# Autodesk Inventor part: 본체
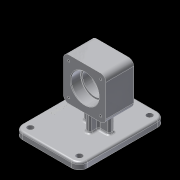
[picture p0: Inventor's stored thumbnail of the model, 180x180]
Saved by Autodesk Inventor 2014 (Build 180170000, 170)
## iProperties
Created: 2020-11
Part Number: 본체
Material: 알루미늄 6061
Document SubType Name: Modeling
Designer: kh
Density: 2.71 g/cm^3
Appearance: 알루미늄 - 평지
Mass: 685.745 g
Surface Area: 542.794 cm^2
Volume: 253.042 cm^3
Author: kh
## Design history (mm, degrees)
sketch "스케치1"
  geometry: L1 (65, 49)-(-65, 49); L2 (-65, 49)-(-65, -49); L3 (-65, -49)-(65, -49); L4 (65, -49)-(65, 49); L5 (65, 49)-(-65, -49); L6 (-65, 49)-(65, -49); 1 further point
  constraints: 12 end point, 2 midpoint, 2 parallel, 1 horizontal, 1 perpendicular
  dimensions: "d0" = 130 distance between parallel lines of L2 L4; "d1" = 98 distance between parallel lines of L1 L3
extrude "돌출1" new body sketch "스케치1" distance "d2" = 10; taper "d3" = 0 deg
sketch "스케치2"
  geometry: L1 (102, 45)-(38, 45); L2 (38, 45)-(38, -19); L3 (38, -19)-(102, -19); L4 (102, -19)-(102, 45); L5 (102, 45)-(38, -19); L6 (38, 45)-(102, -19); L7 (0, -49)-(10, -49) reference; 2 further points
  constraints: 12 end point, 2 midpoint, 2 parallel, 1 horizontal, 1 perpendicular
  dimensions: "d4" = 64 distance between parallel lines of L3 L1; "d5" = 70 horizontal distance of point (0, 0) point (70, 13); "d6" = 62 distance from line of L7 point (70, 13); "d7" = 64 distance between parallel lines of L2 L4
extrude "돌출2" join sketch "스케치2" stored distance "d8" = 42; taper "d9" = 0 deg
fillet "모깎기1" dims "d10" = 12
hole "구멍1" diameter "d13" = 9; stored, may be unused: countersink angle "d17" = 90 deg, drill point angle "d19" = 118 deg; dims "d11" = 10, "d12" = 10, "d14" = 6, "d15" = 4, "d16" = 2, "d18" = 8
fillet "모깎기2" dims "d24" = 8
sketch "스케치3"
  geometry: L1 (37, 102)-(-11, 102) reference; L2 (-19, 94)-(-19, 46) reference; 4 further points
  constraints: 2 midpoint, 1 horizontal alignment, 1 vertical alignment
hole "구멍2" sketch "스케치3" at (13, 70) diameter "d25" = 36; stored, may be unused: countersink angle "d29" = 90 deg, drill point angle "d31" = 118 deg; dims "d26" = 6, "d27" = 42, "d28" = 15, "d30" = 8
hole "구멍3" diameter "d34" = 42; stored, may be unused: countersink angle "d38" = 90 deg, drill point angle "d40" = 0 deg; dims "d32" = 10, "d33" = 10, "d35" = 6, "d36" = 42, "d37" = 15, "d39" = 15
fillet "모깎기3" dims "d41" = 0.3
chamfer "모따기1" distance "d42" = 1; stored, may be unused: second distance "d43" = 2, angle "d44" = 45 deg
sketch "스케치4"
  geometry: L1 (38, -7)-(10, -7); L2 (38, 33)-(10, 33); L3 (10, 37)-(10, -37) reference; L4 (38, 37)-(38, -11) reference; L5 (70, 13)-(-11.805, 13); L6 (38, -7)-(38, 33); L7 (10, -7)-(10, 33); C1 r 18 at (70, 13) reference; 1 further point
  constraints: 10 end point, 4 point on line, 2 parallel, 1 collinear, 1 horizontal, 1 perpendicular, 1 other
  dimensions: "d45" = 40 distance between parallel lines of L2 L1
extrude "돌출3" join sketch "스케치4" stored distance "d46" = 8; taper "d47" = 0 deg
node "작업 평면1"
sketch "스케치5"
  geometry: L1 (-13, 31.88)-(-13, -5.248); 1 further point
  constraints: 2 end point, 1 vertical
  dimensions: "d48" = 17 distance from line of point (4, -10) L1
feature "리브1" sketch "스케치5" dims "d49" = 1, "d50" = 8, "d51" = 0, "d52" = 0, "d53" = 1, "d54" = 1
hole "구멍4" diameter "d57" = 3.242; stored, may be unused: countersink angle "d61" = 90 deg, drill point angle "d63" = 118 deg; dims "d55" = 10, "d56" = 10, "d58" = 8, "d59" = 42, "d60" = 15, "d62" = 10
fillet "모깎기4" dims "d68" = 3
fillet "모깎기5" dims "d69" = 3
fillet "모깎기6" dims "d70" = 3
sketch "스케치6"
  geometry: L1 (53, 49)-(-53, 49) reference; L2 (65, -37)-(65, 37) reference; 3 further points
  constraints: 1 midpoint, 1 vertical alignment, 1 other
  dimensions: "d71" = 10 distance from line of point (0, 39) L1
feature "엠보싱1" sketch "스케치6" dims "d0" = 130, "d1" = 98, "d73" = 0.5, "d74" = 0
node "솔리드1"
pattern_linear "직사각형 패턴1"
mirror "대칭1"
pattern_linear "직사각형 패턴2"
mirror "대칭2"
